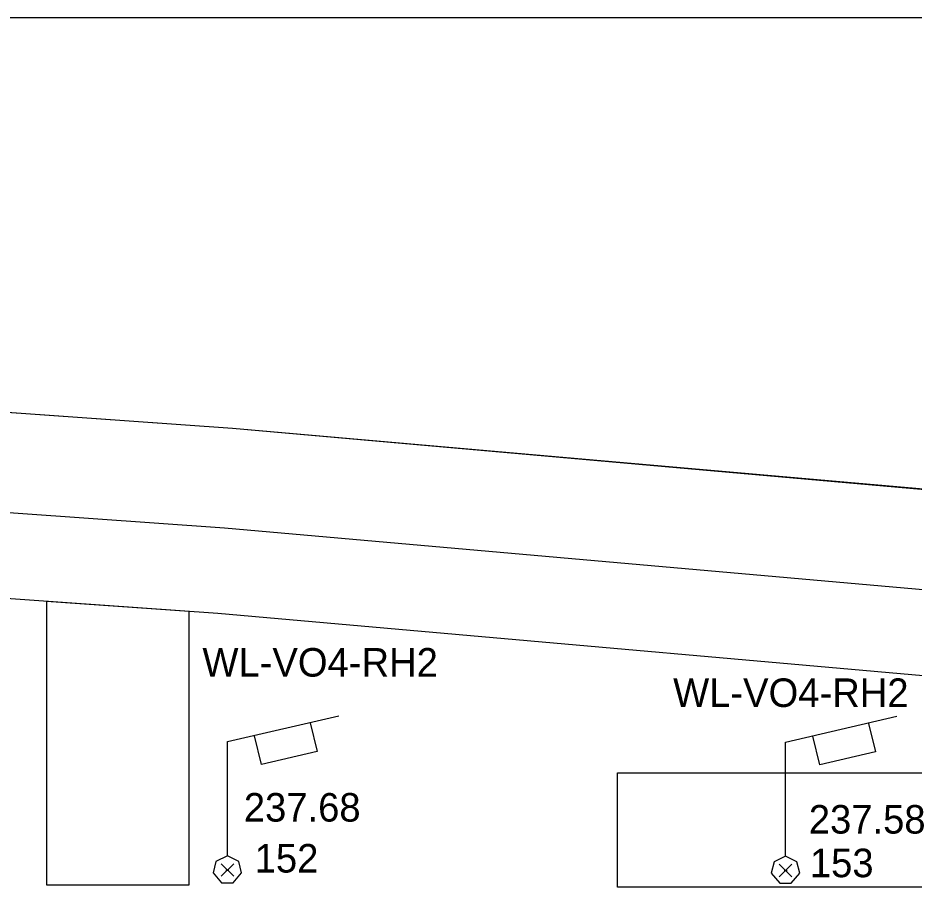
# Model space of a CAD drawing. Extents: x -264222 to -263592, y -1242345 to -1242048.
# Drawn here: x -263902.97 to -263871.58, y -1242078.38 to -1242047.94 of the extents above; entities that cross this region are included whole.
import ezdxf

# ---------------------------------------------------------------- set-up
doc = ezdxf.new("R2010")
doc.units = 0
for name, color, linetype in [('BOD_CISLO', 7, 'Continuous'), ('BOD_SYMBOL', 7, 'Continuous'), ('BOD_VYSKA', 7, 'Continuous'), ('KFA_2D_SITUACIA_DSP', 7, 'Continuous'), ('KFA_SO_62-1_VO_LAMPY_MERANE', 7, 'Continuous'), ('KFA_SO_62-1_VO_POPIS_LAMP_PROJEKT', 7, 'Continuous'), ('RAM_NA_TLAC_1-500', 7, 'Continuous')]:
    doc.layers.add(name, color=color, linetype=linetype)

msp = doc.modelspace()

# ---------------------------------------------------------------- linework, layer by layer
at = {"layer": 'BOD_SYMBOL'}
for p, q in [((-263895.855, -1242078.006), (-263895.413, -1242077.564)), ((-263895.413, -1242078.006), (-263895.855, -1242077.564)), ((-263876.3, -1242078.022), (-263875.858, -1242077.58)), ((-263875.858, -1242078.022), (-263876.3, -1242077.58))]:
    msp.add_line(p, q, dxfattribs=at)
at = {"layer": 'KFA_2D_SITUACIA_DSP'}
for p, q in [((-263895.455, -1242062.322), (-263915.197, -1242060.921)), ((-263866.964, -1242064.823), (-263895.455, -1242062.322)), ((-263896.968, -1242068.731), (-263901.968, -1242068.376)), ((-263901.968, -1242068.376), (-263901.968, -1242074.382)), ((-263896.968, -1242074.382), (-263896.968, -1242068.731)), ((-263901.968, -1242074.382), (-263901.968, -1242078.308)), ((-263896.968, -1242078.308), (-263896.968, -1242074.382)), ((-263901.968, -1242078.308), (-263896.968, -1242078.308))]:
    msp.add_line(p, q, dxfattribs=at)
for points in [[(-263863.949, -1242065.106), (-263895.455, -1242062.322), (-263915.197, -1242060.921), (-263926.771, -1242063.254), (-263950.745, -1242062.149), (-263959.468, -1242059.534)], [(-263864.257, -1242068.593), (-263895.733, -1242065.811), (-263914.971, -1242064.445), (-263926.501, -1242066.77), (-263951.337, -1242065.625), (-263959.611, -1242063.145)], [(-263864.521, -1242071.581), (-263895.971, -1242068.802), (-263914.777, -1242067.467), (-263926.271, -1242069.784), (-263951.845, -1242068.605), (-263959.611, -1242066.277)]]:
    msp.add_lwpolyline(points, dxfattribs=at)
msp.add_lwpolyline([(-263881.968, -1242074.382), (-263866.968, -1242074.382), (-263866.968, -1242078.382), (-263881.968, -1242078.382)], close=True, dxfattribs=at)
at = {"layer": 'KFA_SO_62-1_VO_LAMPY_MERANE'}
for p, q in [((-263895.684, -1242077.785), (-263895.584, -1242077.785)), ((-263895.634, -1242077.785), (-263895.634, -1242077.785)), ((-263876.129, -1242077.801), (-263876.029, -1242077.801)), ((-263876.079, -1242077.801), (-263876.079, -1242077.801))]:
    msp.add_line(p, q, dxfattribs=at)
for points in [[(-263895.634, -1242077.285), (-263896.034, -1242077.485), (-263896.134, -1242077.885), (-263895.834, -1242078.235), (-263895.434, -1242078.235), (-263895.134, -1242077.885), (-263895.234, -1242077.485), (-263895.634, -1242077.285), (-263895.634, -1242073.285), (-263891.734, -1242072.385)], [(-263876.079, -1242077.301), (-263876.479, -1242077.501), (-263876.579, -1242077.901), (-263876.279, -1242078.251), (-263875.879, -1242078.251), (-263875.579, -1242077.901), (-263875.679, -1242077.501), (-263876.079, -1242077.301), (-263876.079, -1242073.301), (-263872.179, -1242072.401)], [(-263892.734, -1242072.635), (-263892.484, -1242073.635), (-263894.434, -1242074.085), (-263894.684, -1242073.085)], [(-263873.179, -1242072.651), (-263872.929, -1242073.651), (-263874.879, -1242074.101), (-263875.129, -1242073.101)]]:
    msp.add_lwpolyline(points, dxfattribs=at)
at = {"layer": 'RAM_NA_TLAC_1-500'}
msp.add_lwpolyline([(-264221.898, -1242344.938), (-263591.898, -1242344.938), (-263591.898, -1242047.938), (-264221.898, -1242047.938)], close=True, dxfattribs=at)

# ---------------------------------------------------------------- texts
at = {"layer": 'BOD_CISLO'}
for s, p in [('152', (-263894.677, -1242077.874)), ('153', (-263875.228, -1242078.037))]:
    msp.add_text(s, height=1, dxfattribs=at).set_placement(p)
at = {"layer": 'BOD_VYSKA'}
for s, p in [('237.68', (-263895.057, -1242076.089)), ('237.58', (-263875.265, -1242076.509))]:
    msp.add_text(s, height=1, dxfattribs=at).set_placement(p)
at = {"layer": 'KFA_SO_62-1_VO_POPIS_LAMP_PROJEKT'}
for p in [(-263896.507, -1242071.01), (-263880.018, -1242072.074)]:
    msp.add_text('WL-VO4-RH2', height=1, dxfattribs=at).set_placement(p)

doc.saveas('drawing.dxf')
